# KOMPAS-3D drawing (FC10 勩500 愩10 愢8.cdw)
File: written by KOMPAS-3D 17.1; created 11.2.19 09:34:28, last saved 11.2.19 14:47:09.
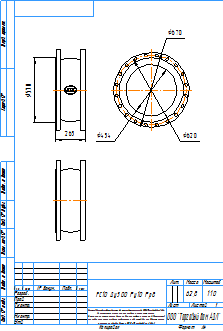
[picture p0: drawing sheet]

Sheet 1: A4, portrait

Title block, sheet 1: name: FC10 Ду500 Ру10 Рр8; mass: 62,8; sheets: 1; sheet format: A4; stored path: \\adlc.lan\data\АДЛ_ПКД\3D-модели\ADL production\Гибкие вставки серии FC\FC10\KOMPAS 2D\FC10 Ду500 Ру10 Рр8.cdw

Views: Вид 1
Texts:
  kka
  adl
  Рама для чертежей
  Лит-Масса-Масштаб
  Материал-Предприятие
  Масштаб
  Изм.
  Лист
  № докум.
  Подп.
  Дата
  Лит.
  Разраб.
  Пров.
  Т.контр.
  Листов
  Внимание! Данный продукт является объектом авторского права ООО «Торговый Дом АДЛ».
  Запрещается изменение, копирование, распространение
  (в том числе путем копирования на другие сайты и ресурсы в Интернете)
  или любое иное использование информации и объектов без предварительного
  согласия правообладателя (ООО «Торговый Дом АДЛ»).
  Н.контр.
  Утв.
  ООО "Торговый дом АДЛ"
  Изменение
  Номер документа
  Подпись
  Обозначение документа
  Наименование изделия
  Масса изделия по ГОСТ 2.109-73
  Порядковый номер листа
  Общее количество листов в документе
  Характер работы, выполненной лицом, подписавшим документ
  Наименование или индекс предприятия, выпускающего документ
  Инв. № подл.
  Подп. и дата
  Взам. инв. №
  Инв. № дубл.
  Инвентарный номер подлинника по ГОСТ 2.501-68
  Подпись принявшего подлинник в отдел технической документации
  Инвентарный номер подлинника, взамен которого выпущен данный подлинник
  Инвентарный номер дубликата по ГОСТ 2.502-68
  Подпись принявшего дубликат в отдел технической документации
  Справ. №
  Перв. примен.
  Обозначение документа, взамен или на основании которого выпущен данный документ
  Обозначение документа, в котором впервые записан данный документ
  Подпись лица, копировавшего чертеж
  Обозначение формата листа
  !Рама для чертежа
Dimensions and other numbers on the sheet: 265; 570; 454; 620; 670; 1:10; 1; 62,8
